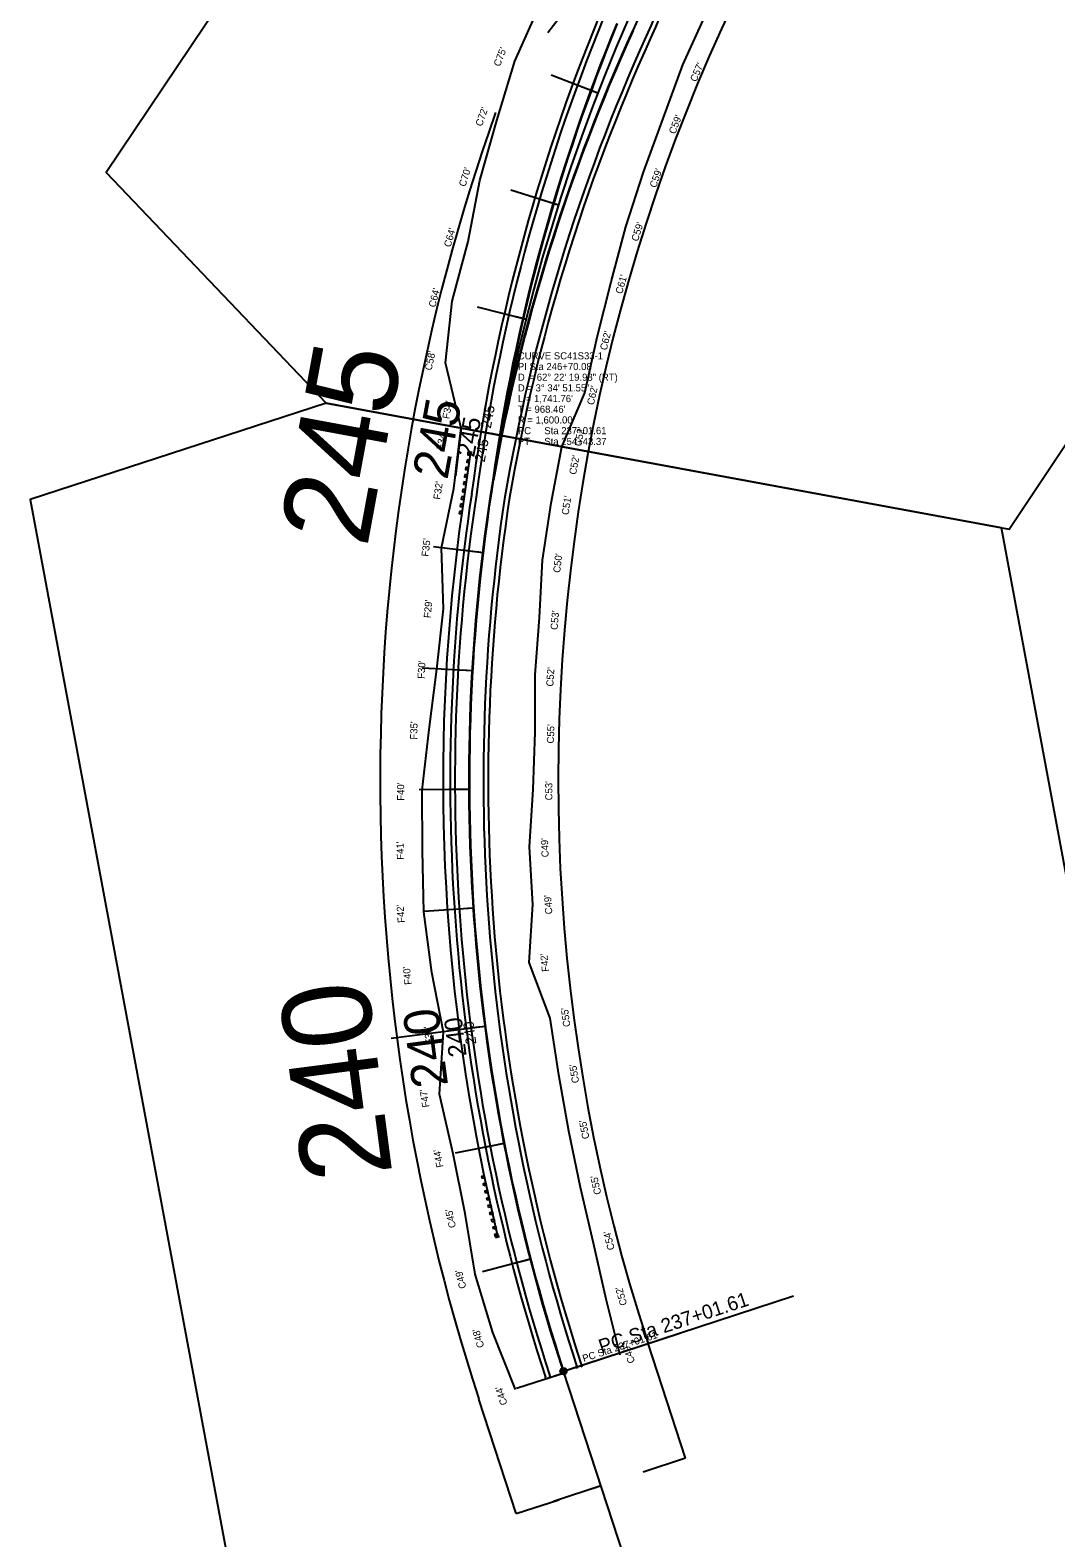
# Model space of a CAD drawing. Extents: x 2358865 to 2362945, y 393485 to 404880.
# Drawn here: x 2358865 to 2359729, y 396293 to 397563 of the extents above; entities that cross this region are included whole.
import ezdxf

# ---------------------------------------------------------------- set-up
doc = ezdxf.new("R2010")
doc.units = 0
for name, color, linetype in [('CL', 7, 'Continuous'), ('Level 11', 7, 'Continuous'), ('Level 12', 7, 'Continuous'), ('Level 19', 7, 'Continuous'), ('Level 22', 7, 'Continuous'), ('Level 25', 7, 'Continuous'), ('Level 27', 7, 'Continuous'), ('Level 28', 7, 'Continuous'), ('Level 30', 7, 'Continuous'), ('Level 33', 7, 'Continuous'), ('Level 37', 7, 'Continuous'), ('Level 39', 7, 'Continuous'), ('Level 40', 7, 'Continuous'), ('Level 41', 7, 'Continuous'), ('Level 48', 7, 'Continuous'), ('Level 50', 7, 'Continuous'), ('Level 51', 7, 'Continuous'), ('Level 52', 7, 'Continuous'), ('Level 53', 7, 'Continuous'), ('Level 61', 7, 'Continuous'), ('Level 63', 7, 'Continuous')]:
    doc.layers.add(name, color=color, linetype=linetype)

msp = doc.modelspace()

# ---------------------------------------------------------------- linework, layer by layer
at = {"layer": 'CL'}
msp.add_line((2360255.9, 393557.3), (2359314.4, 396433.7), dxfattribs=at)
msp.add_arc((2360835, 396931.4), 1600, 135.7519, 198.1241, dxfattribs=at)
at = {"layer": 'Level 11'}
for p, q in [((2359330.1, 396437.1), (2359329.6, 396438.6)), ((2359299.7, 396427.2), (2359299.2, 396428.7))]:
    msp.add_line(p, q, dxfattribs=at)
for centre, radius, start, end in [((2360835, 396931.4), 1576.5, 144.775, 156.6363), ((2360842.5, 396959.6), 1619.5, 157.6583, 172.4347), ((2360826.5, 396903.5), 1580, 155.585, 170.3628), ((2360835, 396931.4), 1616, 171.4065, 198.1241), ((2360835, 396931.4), 1584, 171.4065, 198.1241)]:
    msp.add_arc(centre, radius, start, end, dxfattribs=at)
at = {"layer": 'Level 12'}
for p, q in [((2359234.1, 397208.3), (2359237.2, 397207.9)), ((2359234.9, 397206.4), (2359234.1, 397208.3)), ((2359234.2, 397208.1), (2359237, 397207.7)), ((2359235.9, 397206.3), (2359237.2, 397207.9)), ((2359235.9, 397206.3), (2359228.8, 397156.8)), ((2359235.9, 397206.3), (2359228.8, 397156.8)), ((2359258.8, 396548.6), (2359247.8, 396597.4)), ((2359258.8, 396548.6), (2359247.8, 396597.4)), ((2359257.9, 396548.4), (2359257.2, 396546.4)), ((2359257.3, 396546.7), (2359260.1, 396547.3)), ((2359258.8, 396548.6), (2359260.3, 396547.1)), ((2359257.2, 396546.4), (2359260.3, 396547.1))]:
    msp.add_line(p, q, dxfattribs=at)
for points in [[(2359232.3, 397195.2), (2359232, 397193.2), (2359234, 397192.9), (2359234.2, 397194.9)], [(2359233.2, 397201.3), (2359232.9, 397199.4), (2359234.9, 397199.1), (2359235.1, 397201.1)], [(2359234, 397207.5), (2359233.8, 397205.5), (2359235.7, 397205.3), (2359236, 397207.2)], [(2359230.5, 397182.8), (2359230.2, 397180.8), (2359232.2, 397180.5), (2359232.5, 397182.5)], [(2359231.4, 397189), (2359231.1, 397187), (2359233.1, 397186.7), (2359233.4, 397188.7)], [(2359228.7, 397170.4), (2359228.4, 397168.4), (2359230.4, 397168.1), (2359230.7, 397170.1)], [(2359229.6, 397176.6), (2359229.3, 397174.6), (2359231.3, 397174.3), (2359231.6, 397176.3)], [(2359226.9, 397158), (2359226.6, 397156.1), (2359228.6, 397155.8), (2359228.9, 397157.8)], [(2359227.8, 397164.2), (2359227.5, 397162.2), (2359229.5, 397162), (2359229.8, 397163.9)], [(2359246.1, 396596), (2359245.6, 396597.9), (2359247.6, 396598.4), (2359248, 396596.4)], [(2359247.4, 396589.9), (2359247, 396591.8), (2359248.9, 396592.3), (2359249.4, 396590.3)], [(2359248.8, 396583.8), (2359248.4, 396585.7), (2359250.3, 396586.2), (2359250.8, 396584.2)], [(2359250.2, 396577.7), (2359249.8, 396579.6), (2359251.7, 396580.1), (2359252.1, 396578.1)], [(2359251.6, 396571.6), (2359251.1, 396573.6), (2359253.1, 396574), (2359253.5, 396572)], [(2359253, 396565.5), (2359252.5, 396567.5), (2359254.5, 396567.9), (2359254.9, 396566)], [(2359254.3, 396559.4), (2359253.9, 396561.4), (2359255.9, 396561.8), (2359256.3, 396559.9)], [(2359255.7, 396553.3), (2359255.3, 396555.3), (2359257.2, 396555.7), (2359257.7, 396553.8)], [(2359257.1, 396547.2), (2359256.7, 396549.2), (2359258.6, 396549.6), (2359259.1, 396547.7)]]:
    msp.add_lwpolyline(points, close=True, dxfattribs=at)
msp.add_arc((2360835, 396931.4), 1622, 172.0131, 191.8829, dxfattribs=at)
at = {"layer": 'Level 19'}
for p, q in [((2359326.3, 396435.9), (2359325.8, 396437.4)), ((2359303.5, 396428.4), (2359303, 396429.9))]:
    msp.add_line(p, q, dxfattribs=at)
for centre, radius, start, end in [((2360835, 396931.4), 1580.5, 144.775, 156.635), ((2360842.5, 396959.6), 1615.5, 157.6583, 172.4347), ((2360826.5, 396903.5), 1584, 155.5863, 170.3628), ((2360835, 396931.4), 1612, 171.4065, 198.1241), ((2360835, 396931.4), 1588, 171.4065, 198.1241)]:
    msp.add_arc(centre, radius, start, end, dxfattribs=at)
at = {"layer": 'Level 25'}
for p, q in [((2359343.4, 397510.2), (2359338.7, 397512)), ((2359310.2, 397415.9), (2359305.4, 397417.4)), ((2359282.9, 397319.7), (2359278, 397321)), ((2359261.6, 397222), (2359253.8, 397223.5)), ((2359246.6, 397123.2), (2359241.6, 397123.8)), ((2359237.7, 397023.6), (2359232.7, 397023.9)), ((2359235, 396923.7), (2359230, 396923.6)), ((2359238.6, 396823.7), (2359233.7, 396823.4)), ((2359248.5, 396724.2), (2359240.6, 396723.2)), ((2359264.5, 396625.6), (2359259.6, 396624.6)), ((2359286.7, 396528.1), (2359281.9, 396526.8)), ((2359314.9, 396432.1), (2359310.2, 396430.6)), ((2359346, 396337.1), (2359341.3, 396335.5))]:
    msp.add_line(p, q, dxfattribs=at)
at = {"layer": 'Level 27'}
for p, q in [((2359417.3, 396360.4), (2359385.7, 396457)), ((2359274.7, 396313.8), (2359243.1, 396410.3)), ((2359417.3, 396360.4), (2359381.7, 396348.8)), ((2359274.7, 396313.8), (2359310.4, 396325.4))]:
    msp.add_line(p, q, dxfattribs=at)
for radius, start in [(1525, 137.3051), (1675, 160.3756)]:
    msp.add_arc((2360835, 396931.4), radius, start, 198.1241, dxfattribs=at)
at = {"layer": 'Level 28'}
msp.add_line((2359315.6, 396434.1), (2359412.4, 396465.8), dxfattribs=at)
msp.add_circle((2359314.4, 396433.7), 1.25, dxfattribs=at)
at = {"layer": 'Level 30'}
for p, q in [((2359343.4, 397510.2), (2359335.5, 397513.3)), ((2359310.2, 397415.9), (2359302.1, 397418.5)), ((2359282.9, 397319.7), (2359274.6, 397321.8)), ((2359261.6, 397222), (2359245.9, 397224.9)), ((2359246.6, 397123.2), (2359238.1, 397124.2)), ((2359237.7, 397023.6), (2359229.2, 397024.1)), ((2359235, 396923.7), (2359226.5, 396923.6)), ((2359238.6, 396823.7), (2359230.2, 396823.2)), ((2359248.5, 396724.2), (2359232.6, 396722.2)), ((2359264.5, 396625.6), (2359256.2, 396623.9)), ((2359286.7, 396528.1), (2359278.5, 396525.9)), ((2359314.9, 396432.1), (2359306.8, 396429.5)), ((2359346, 396337.1), (2359337.9, 396334.5))]:
    msp.add_line(p, q, dxfattribs=at)
at = {"layer": 'Level 33'}
msp.add_line((2359317, 396434.5), (2359508.3, 396497.1), dxfattribs=at)
msp.add_circle((2359314.4, 396433.7), 2.7, dxfattribs=at)
at = {"layer": 'Level 37'}
for p, q in [((2359314.7, 396432.1), (2359314.2, 396433.6)), ((2359315.1, 396432.2), (2359314.6, 396433.7))]:
    msp.add_line(p, q, dxfattribs=at)
for centre, radius, start, end in [((2358612.3, 397919.1), 840, 334.9269, 341.4689), ((2360842.5, 396959.6), 1603.5, 157.6621, 171.9446), ((2360842.5, 396959.6), 1603, 157.6621, 171.4513), ((2360826.5, 396903.5), 1596.5, 155.5877, 169.3752), ((2360826.5, 396903.5), 1596, 155.5874, 169.8706), ((2360835, 396931.4), 1600.3, 170.9078, 198.1241), ((2360835, 396931.4), 1599.8, 170.9077, 198.1241)]:
    msp.add_arc(centre, radius, start, end, dxfattribs=at)
at = {"layer": 'Level 39'}
for p, q in [((2359343.4, 397510.2), (2359327.5, 397516.4)), ((2359310.2, 397415.9), (2359294, 397421.1)), ((2359282.9, 397319.7), (2359266.4, 397323.9)), ((2359261.6, 397222), (2359230.2, 397227.8)), ((2359246.6, 397123.2), (2359229.7, 397125.2)), ((2359237.7, 397023.6), (2359220.7, 397024.6)), ((2359235, 396923.7), (2359218, 396923.6)), ((2359238.6, 396823.7), (2359221.7, 396822.6)), ((2359248.5, 396724.2), (2359216.8, 396720.1)), ((2359264.5, 396625.6), (2359247.8, 396622.3)), ((2359286.7, 396528.1), (2359270.2, 396523.8)), ((2359314.9, 396432.1), (2359298.8, 396426.8)), ((2359346, 396337.1), (2359329.9, 396331.8))]:
    msp.add_line(p, q, dxfattribs=at)
at = {"layer": 'Level 40'}
msp.add_line((2359556.8, 397893.8), (2359301.4, 397561), dxfattribs=at)
at = {"layer": 'Level 41'}
for p, q in [((2359343.4, 397510.2), (2359304.2, 397525.4)), ((2359310.2, 397415.9), (2359270.1, 397428.6)), ((2359282.9, 397319.7), (2359242.1, 397329.9)), ((2359261.6, 397222), (2359183, 397236.6)), ((2359246.6, 397123.2), (2359204.9, 397128.2)), ((2359237.7, 397023.6), (2359195.8, 397026)), ((2359235, 396923.7), (2359193, 396923.5)), ((2359238.6, 396823.7), (2359196.7, 396820.9)), ((2359248.5, 396724.2), (2359169.2, 396713.9)), ((2359264.5, 396625.6), (2359223.3, 396617.5)), ((2359286.7, 396528.1), (2359246.1, 396517.5)), ((2359314.9, 396432.1), (2359275, 396419.1)), ((2359346, 396337.1), (2359306.1, 396324))]:
    msp.add_line(p, q, dxfattribs=at)
at = {"layer": 'Level 48'}
for centre, radius, start, end in [((2360842.5, 396959.6), 1603, 157.6623, 171.4513), ((2360826.5, 396903.5), 1596.5, 155.5877, 169.3752)]:
    msp.add_arc(centre, radius, start, end, dxfattribs=at)
at = {"layer": 'Level 50'}
for p, q in [((2359273.5, 397537.2), (2359294.9, 397585)), ((2359415.1, 397534.1), (2359435, 397578)), ((2359258.2, 397487.2), (2359273.5, 397537.2)), ((2359398.4, 397488.8), (2359415.1, 397534.1)), ((2359244.1, 397436.8), (2359258.2, 397487.2)), ((2359382, 397443.6), (2359398.4, 397488.8)), ((2359234.2, 397385.4), (2359244.1, 397436.8)), ((2359367, 397397.8), (2359382, 397443.6)), ((2359354.6, 397351.3), (2359367, 397397.8)), ((2359220.8, 397335.1), (2359234.2, 397385.4)), ((2359342.9, 397304.6), (2359354.6, 397351.3)), ((2359215.1, 397283.2), (2359220.8, 397335.1)), ((2359332.4, 397257.7), (2359342.9, 397304.6)), ((2359313.1, 397212.4), (2359332.4, 397257.7)), ((2359304.1, 397164.9), (2359313.1, 397212.4)), ((2359296.8, 397117), (2359304.1, 397164.9)), ((2359294.3, 397068.6), (2359296.8, 397117)), ((2359290.5, 397020.4), (2359294.3, 397068.6)), ((2359290.6, 396972), (2359290.5, 397020.4)), ((2359289, 396923.7), (2359290.6, 396972)), ((2359285.7, 396875.3), (2359289, 396923.7)), ((2359288.5, 396826.9), (2359285.7, 396875.3)), ((2359310.4, 396683.4), (2359303.2, 396731.1)), ((2359319, 396635.9), (2359310.4, 396683.4)), ((2359328.8, 396588.6), (2359319, 396635.9)), ((2359339.8, 396541.6), (2359328.8, 396588.6)), ((2359240, 396515.5), (2359231.7, 396566.5)), ((2359350.3, 396494.3), (2359339.8, 396541.6)), ((2359254.8, 396466.2), (2359240, 396515.5)), ((2359362.3, 396447.2), (2359350.3, 396494.3)), ((2359273.9, 396418.3), (2359254.8, 396466.2))]:
    msp.add_line(p, q, dxfattribs=at)
at = {"layer": 'Level 51'}
for p, q in [((2359222.1, 397177.3), (2359228.4, 397228)), ((2359211.7, 397127.2), (2359222.1, 397177.3)), ((2359213.3, 397075.8), (2359211.7, 397127.2)), ((2359207.9, 397025.1), (2359213.3, 397075.8)), ((2359201.4, 396974.3), (2359207.9, 397025.1)), ((2359195.4, 396923.2), (2359201.4, 396974.3)), ((2359195.8, 396872), (2359195.4, 396923.2)), ((2359196.9, 396820.7), (2359195.8, 396872)), ((2359203.5, 396769.7), (2359196.9, 396820.7)), ((2359213.4, 396719.4), (2359203.5, 396769.7)), ((2359210, 396667), (2359213.4, 396719.4)), ((2359221.6, 396616.8), (2359210, 396667))]:
    msp.add_line(p, q, dxfattribs=at)
at = {"layer": 'Level 52'}
for p, q in [((2359228.4, 397228), (2359215.1, 397283.2)), ((2359285.5, 396777.9), (2359288.5, 396826.9)), ((2359303.2, 396731.1), (2359285.5, 396777.9)), ((2359231.7, 396566.5), (2359221.6, 396616.8))]:
    msp.add_line(p, q, dxfattribs=at)
at = {"layer": 'Level 61'}
for p, q in [((2359228.4, 397228.1), (2359223.4, 397187.7)), ((2359224.1, 397194.6), (2359228.4, 397228.1)), ((2359223.4, 397187.7), (2359224.1, 397194.6))]:
    msp.add_line(p, q, dxfattribs=at)
at = {"layer": 'Level 63'}
for points in [[(2360368.8, 398162.6), (2359965.3, 398555.6), (2359965.3, 398555.6), (2359790.8, 398725.6), (2358929.1, 397443.5), (2359114.5, 397249), (2359262, 397221.8), (2359690, 397143), (2359690, 397143)], [(2359683.4, 397144.2), (2359262, 397221.8), (2359114.5, 397249), (2358865.2, 397167.9), (2359144, 395672.2), (2359537.3, 395745.5), (2359930.5, 395818.9), (2359916.8, 395892.1)]]:
    msp.add_lwpolyline(points, close=True, dxfattribs=at)

# ---------------------------------------------------------------- texts
at = {"layer": 'Level 22'}
for s, p in [('CURVE SC41S33-1', (2359276, 397286)), ('PI Sta 246+70.08', (2359276, 397277)), ('D', (2359276, 397268)), ('= 62%%d 22\' 19.98" (RT)', (2359285, 397268)), ('D = 3%%d 34\' 51.55"', (2359276, 397259)), ("T = 968.46'", (2359276, 397241)), ("L = 1,741.76'", (2359276, 397250)), ("R = 1,600.00'", (2359276, 397232)), ('PC', (2359276, 397223)), ('Sta 237+01.61', (2359298.3, 397223)), ('PT', (2359276, 397214)), ('Sta 254+43.37', (2359298.3, 397213.9))]:
    msp.add_text(s, height=6, dxfattribs=at).set_placement(p)
at = {"layer": 'Level 25'}
for s, rotation, p in [('245', 79.534, (2359253.2, 397227.4)), ('245', 79.534, (2359248, 397199)), ('240', 97.439, (2359241.1, 396709.5))]:
    msp.add_text(s, height=8.75, rotation=rotation, dxfattribs=at).set_placement(p)
at = {"layer": 'Level 28'}
msp.add_text('PC Sta 237+01.61', height=6, rotation=18.1241, dxfattribs=at).set_placement((2359331.6, 396441.4))
at = {"layer": 'Level 30'}
for s, rotation, p in [('245', 79.534, (2359239.1, 397203)), ('240', 97.439, (2359232.9, 396699.4))]:
    msp.add_text(s, height=15, rotation=rotation, dxfattribs=at).set_placement(p)
at = {"layer": 'Level 33'}
msp.add_text('PC Sta 237+01.61', height=12, rotation=18.1241, dxfattribs=at).set_placement((2359346.4, 396448.4))
at = {"layer": 'Level 39'}
for s, rotation, p in [('245', 79.534, (2359216.6, 397184)), ('240', 97.439, (2359217.3, 396674.6))]:
    msp.add_text(s, height=30, rotation=rotation, dxfattribs=at).set_placement(p)
at = {"layer": 'Level 41'}
for s, rotation, p in [('245', 79.534, (2359148.9, 397126.6)), ('240', 97.439, (2359170.4, 396599.8))]:
    msp.add_text(s, height=75, rotation=rotation, dxfattribs=at).set_placement(p)
at = {"layer": 'Level 53'}
for s, rotation, p in [("C75'", 68.7931, (2359260.9, 397532.2)), ("C57'", 67.0023, (2359426.3, 397519.3)), ("C72'", 70.584, (2359245.7, 397481.8)), ("C59'", 68.7931, (2359408.5, 397475.3)), ("C70'", 72.3748, (2359231.8, 397431)), ("C59'", 70.584, (2359392.4, 397430.1)), ("C59'", 72.3748, (2359377.1, 397384.9)), ("C64'", 74.1657, (2359219.3, 397380.1)), ("C61'", 74.1657, (2359363.8, 397340.7)), ("C64'", 75.9566, (2359206.5, 397329.4)), ("C62'", 75.9566, (2359350.8, 397293.3)), ("C58'", 77.7475, (2359203.3, 397276.3)), ("C62'", 77.7475, (2359340, 397247.2)), ("F34'", 79.5384, (2359218.2, 397235.5)), ("F34'", 79.5384, (2359213.2, 397209.4)), ("C52'", 79.5384, (2359329.4, 397212.5)), ("C52'", 79.5384, (2359325, 397188.6)), ("F32'", 81.3294, (2359210.6, 397167.6)), ("C51'", 81.3294, (2359318.7, 397154.6)), ("F35'", 83.1204, (2359200.7, 397119.6)), ("C50'", 83.1204, (2359311.6, 397106)), ("F29'", 84.9114, (2359202.6, 397067.9)), ("C53'", 84.9114, (2359309.4, 397058)), ("F30'", 86.7024, (2359197.4, 397016.8)), ("C52'", 86.7024, (2359305.9, 397010.3)), ("F35'", 88.4934, (2359191.2, 396965.7)), ("C55'", 88.4934, (2359306.4, 396962.4)), ("F40'", 90.2845, (2359180.3, 396914.3)), ("C53'", 90.2845, (2359305.1, 396914.6)), ("F41'", 92.0756, (2359180.2, 396864.7)), ("C49'", 92.0756, (2359302, 396866.7)), ("C49'", 93.8667, (2359305.1, 396818.8)), ("F42'", 93.8667, (2359180.8, 396811.6)), ("F42'", 95.6578, (2359302.3, 396770.5)), ("F40'", 95.6578, (2359186.6, 396759.5)), ("C55'", 97.4489, (2359320.3, 396724.1)), ("F36'", 97.4489, (2359204.6, 396709.4)), ("C55'", 99.24, (2359327.7, 396676.9)), ("F47'", 99.24, (2359201.6, 396656.4)), ("C55'", 101.0312, (2359336.4, 396629.9)), ("F44'", 101.0312, (2359213.5, 396605.9)), ("C55'", 102.8224, (2359346.4, 396583.2)), ("C45'", 102.8224, (2359224, 396555.1)), ("C54'", 104.6136, (2359357.7, 396536.6)), ("C49'", 104.6136, (2359232.7, 396504.1)), ("C52'", 106.4048, (2359368.2, 396490)), ("C48'", 106.4048, (2359247.8, 396454.4)), ("C49'", 108.1241, (2359374.8, 396441.5)), ("C44'", 108.1241, (2359267.4, 396406.2))]:
    msp.add_text(s, height=6, rotation=rotation, dxfattribs=at).set_placement(p)

doc.saveas('drawing.dxf')
